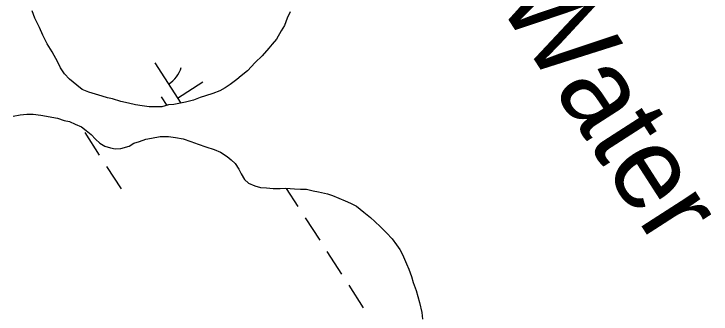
# Model space of a CAD drawing. Extents: x 3937982 to 3958556, y 219448 to 241894.
# Drawn here: x 3944978.9 to 3945395.2, y 231867.9 to 232047.2 of the extents above; entities that cross this region are included whole.
import ezdxf

# ---------------------------------------------------------------- set-up
doc = ezdxf.new("R2010")
doc.units = 0
for name, color, linetype in [('V-RIVR-IDEN', 7, 'Continuous'), ('V-TOPO-SHOR', 7, 'Continuous'), ('V-WETL-SWMP', 7, 'Continuous')]:
    doc.layers.add(name, color=color, linetype=linetype)

msp = doc.modelspace()

# ---------------------------------------------------------------- linework, layer by layer
at = {"layer": 'V-TOPO-SHOR'}
for points in [[(3945143.965, 232048.573), (3945142.04, 232044.625), (3945140.447, 232040.352), (3945138.516, 232037.059), (3945135.62, 232032.12), (3945133.029, 232029.148), (3945131.09, 232026.836), (3945127.207, 232022.213), (3945122.992, 232018.24), (3945118.457, 232013.284), (3945114.56, 232010.298), (3945111.963, 232007.982), (3945108.066, 232004.996), (3945105.139, 232003.001), (3945101.883, 232001.332), (3945097.644, 231999.651), (3945093.4, 231998.299), (3945090.138, 231997.283), (3945086.224, 231995.608), (3945081.325, 231994.576), (3945078.384, 231993.889), (3945074.464, 231993.195), (3945071.194, 231992.835), (3945067.276, 231991.815), (3945063.348, 231991.774), (3945059.745, 231991.737), (3945055.484, 231992.349), (3945051.549, 231992.964), (3945047.283, 231993.904), (3945042.69, 231994.84), (3945037.762, 231996.427), (3945034.811, 231997.052), (3945031.526, 231998), (3945027.586, 231999.27), (3945023.643, 232000.539), (3945019.699, 232002.137), (3945016.4, 232004.721), (3945012.107, 232008.279), (3945009.127, 232011.523), (3945006.801, 232015.101), (3945005.129, 232018.359), (3945001.793, 232024.546), (3944998.797, 232029.424), (3944996.124, 232034.636), (3944994.115, 232039.199), (3944991.441, 232044.737), (3944989.759, 232048.977)], [(3944978.378, 231986.238), (3944982.628, 231986.937), (3944986.552, 231987.303), (3944990.48, 231987.342), (3944995.07, 231986.736), (3944998.35, 231986.113), (3945001.629, 231985.493), (3945004.91, 231984.87), (3945008.853, 231983.6), (3945012.131, 231982.98), (3945015.423, 231981.374), (3945019.367, 231979.779), (3945022.009, 231977.514), (3945024.979, 231975.253), (3945027.627, 231972.332), (3945030.269, 231970.067), (3945033.234, 231968.134), (3945036.519, 231967.184), (3945039.47, 231966.559), (3945042.743, 231966.919), (3945047.64, 231968.277), (3945050.568, 231969.944), (3945053.833, 231970.96), (3945057.747, 231972.31), (3945061.013, 231972.998), (3945066.242, 231974.032), (3945071.153, 231974.081), (3945075.415, 231973.471), (3945080.006, 231972.535), (3945084.606, 231970.944), (3945088.878, 231969.35), (3945093.478, 231967.759), (3945098.406, 231966.174), (3945102.35, 231964.576), (3945106.305, 231961.996), (3945108.617, 231960.057), (3945110.931, 231957.787), (3945113.256, 231954.537), (3945114.595, 231951.604), (3945116.592, 231948.35), (3945118.906, 231946.083), (3945122.852, 231944.486), (3945126.135, 231943.537), (3945129.74, 231943.247), (3945133.67, 231942.958), (3945137.928, 231943.001), (3945141.201, 231943.034), (3945146.441, 231942.759), (3945150.046, 231942.468), (3945153.646, 231942.505), (3945157.585, 231941.563), (3945160.865, 231940.943), (3945166.116, 231939.685), (3945169.072, 231938.733)], [(3945169.072, 231938.733), (3945173.016, 231937.135), (3945176.635, 231935.536), (3945179.92, 231934.26), (3945183.543, 231932.333), (3945187.833, 231928.773), (3945191.796, 231925.54), (3945194.438, 231923.274), (3945197.744, 231920.035), (3945201.381, 231916.471), (3945204.693, 231912.901), (3945207.347, 231909.328), (3945209.342, 231906.401), (3945211.009, 231903.472), (3945213.356, 231897.93), (3945214.697, 231894.67), (3945216.379, 231890.431), (3945217.396, 231886.841), (3945219.084, 231881.946), (3945221.12, 231874.763), (3945222.49, 231868.886), (3945222.856, 231864.96)]]:
    msp.add_lwpolyline(points, dxfattribs=at)
at = {"layer": 'V-WETL-SWMP'}
for p, q in [((3945063.138, 232017.915), (3945078.574, 231993.934)), ((3945076.669, 231996.893), (3945091.804, 232006.636)), ((3945066.934, 231997.762), (3945070.262, 231992.592)), ((3945021.262, 231976.337), (3945029.921, 231962.883)), ((3945034.251, 231956.156), (3945042.911, 231942.702)), ((3945141.52, 231943.017), (3945148.498, 231932.176)), ((3945152.828, 231925.449), (3945161.488, 231911.995)), ((3945165.818, 231905.268), (3945174.478, 231891.814)), ((3945178.808, 231885.087), (3945187.468, 231871.634))]:
    msp.add_line(p, q, dxfattribs=at)
for points in [[(3945055.484, 231992.349), (3945051.549, 231992.964), (3945047.283, 231993.903), (3945042.69, 231994.839), (3945037.763, 231996.426), (3945034.811, 231997.051), (3945031.527, 231998), (3945027.586, 231999.269), (3945023.644, 232000.539), (3945019.699, 232002.136), (3945016.399, 232004.722), (3945012.107, 232008.279), (3945009.128, 232011.523), (3945006.8, 232015.101), (3945005.13, 232018.358), (3945001.793, 232024.545), (3944998.797, 232029.425), (3944996.125, 232034.636), (3944994.115, 232039.199), (3944991.44, 232044.738), (3944989.76, 232048.977)], [(3945143.965, 232048.574), (3945142.04, 232044.625), (3945140.447, 232040.353), (3945138.516, 232037.06), (3945135.619, 232032.12), (3945133.03, 232029.147), (3945131.089, 232026.836), (3945127.207, 232022.213), (3945122.991, 232018.241), (3945118.458, 232013.285), (3945114.56, 232010.299), (3945111.964, 232007.981), (3945108.066, 232004.995), (3945105.139, 232003.001), (3945101.882, 232001.331), (3945097.643, 231999.651), (3945093.401, 231998.298), (3945090.137, 231997.283), (3945086.225, 231995.607), (3945081.325, 231994.575), (3945078.385, 231993.89), (3945074.464, 231993.196), (3945071.194, 231992.835), (3945067.275, 231991.814), (3945063.347, 231991.774), (3945059.746, 231991.737), (3945055.484, 231992.349)], [(3944978.378, 231986.239), (3944982.627, 231986.936), (3944986.552, 231987.303), (3944990.48, 231987.343), (3944995.069, 231986.735), (3944998.35, 231986.113), (3945001.63, 231985.492), (3945004.91, 231984.87), (3945008.852, 231983.601), (3945012.132, 231982.979), (3945015.422, 231981.375), (3945019.367, 231979.778), (3945022.009, 231977.513), (3945024.978, 231975.252), (3945027.627, 231972.332), (3945030.269, 231970.067), (3945033.235, 231968.133)], [(3945033.235, 231968.133), (3945036.519, 231967.184), (3945039.471, 231966.559), (3945042.742, 231966.919), (3945047.639, 231968.278), (3945050.568, 231969.945), (3945053.832, 231970.96), (3945057.747, 231972.309), (3945061.014, 231972.997), (3945066.242, 231974.032), (3945071.152, 231974.082), (3945075.414, 231973.47), (3945080.007, 231972.535), (3945084.607, 231970.944), (3945088.879, 231969.351), (3945093.479, 231967.76), (3945098.406, 231966.173), (3945102.35, 231964.576), (3945106.305, 231961.997), (3945108.617, 231960.056), (3945110.931, 231957.788), (3945113.256, 231954.537), (3945114.595, 231951.605), (3945116.592, 231948.351), (3945118.907, 231946.083), (3945122.852, 231944.486), (3945126.135, 231943.537), (3945129.74, 231943.246), (3945133.671, 231942.958), (3945137.927, 231943.001), (3945141.2, 231943.034), (3945146.442, 231942.76), (3945150.046, 231942.469), (3945153.647, 231942.506), (3945157.585, 231941.563), (3945160.865, 231940.942), (3945166.116, 231939.685), (3945169.072, 231938.733), (3945173.017, 231937.136), (3945176.635, 231935.536), (3945179.921, 231934.259), (3945183.542, 231932.332), (3945187.834, 231928.774), (3945191.796, 231925.54), (3945194.438, 231923.275), (3945197.744, 231920.035), (3945201.382, 231916.47), (3945204.692, 231912.902), (3945207.347, 231909.328), (3945209.341, 231906.402), (3945211.008, 231903.472), (3945213.356, 231897.93), (3945214.698, 231894.67), (3945216.378, 231890.431), (3945217.396, 231886.84), (3945219.083, 231881.946), (3945221.12, 231874.764), (3945222.489, 231868.885), (3945222.856, 231864.96)]]:
    msp.add_lwpolyline(points, dxfattribs=at)
msp.add_arc((3945061.918, 232020.248), 17.623, 301.99668, 343.54034, dxfattribs=at)

# ---------------------------------------------------------------- texts
at = {"layer": 'V-RIVR-IDEN'}
msp.add_text('Water', height=49.9999, rotation=302.76856, dxfattribs=at).set_placement((3945266.673, 232055.434))

doc.saveas('drawing.dxf')
